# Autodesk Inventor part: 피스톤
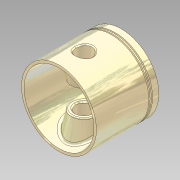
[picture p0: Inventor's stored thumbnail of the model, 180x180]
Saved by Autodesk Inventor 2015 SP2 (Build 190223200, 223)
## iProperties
Manager: KYOUNG IL JANG
Company: 한국ATC센터
Created: 2012-10
Part Number: 피스톤
Document SubType Name: Modeling
Density: 1 g/cm^3
Checked By: KYOUNG IL JANG
Vendor: CBT Solutions
Designer: KYOUNG IL JANG
Material: 일반
Appearance: _시험_금속-티타늄(광택)
Author: KYOUNG IL JANG
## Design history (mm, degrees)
sketch "스케치1"
  geometry: L1 (0, 0)-(0, 50); L2 (0, 50)-(30, 50); L3 (30, 50)-(30, 45); L4 (30, 45)-(28, 45); L5 (28, 45)-(28, 44); L6 (28, 44)-(30, 44); L7 (30, 44)-(30, 43); L8 (30, 43)-(28, 43); L9 (28, 43)-(28, 42); L10 (28, 42)-(30, 42); L11 (30, 42)-(30, 0); L12 (30, 0)-(28, 0); L13 (28, 0)-(23, 45); L14 (23, 45)-(0, 45)
  constraints: 28 end point, 10 parallel, 5 collinear, 2 perpendicular, 2 point on line, 1 vertical
  dimensions: "d0" = 50 distance of L1.start L1.end; "d1" = 60 diameter of L3 L1; "d2" = 5 distance between parallel lines of L2 L14; "d3" = 2 distance of L11.end L12.end; "d5" = 5 distance of L2.end L3.end; "d6" = 1 distance of L4.end L5.end; "d7" = 2 distance of L9.end L10.end; "d26" = 46 diameter of L13.end L1
revolve "회전1" sketch "스케치1" stored, may be unused: angle "d8" = 90 deg
node "작업 평면1"
sketch "스케치2"
  geometry: L1 (-28, 0)-(28, 0) reference; C1 r 10 at (0, 20); C2 r 6.5 at (0, 20); 1 further point
  constraints: 2 centre point, 1 coincident, 1 vertical alignment
  dimensions: "d10" = 20 diameter of C1; "d13" = 20 distance from line of C1.centre L1; "d14" = 13 diameter of C2
extrude "돌출1" join sketch "스케치2" stored distance "d11" = 10; taper "d12" = 12 deg
extrude "돌출2" cut sketch "스케치2" stored distance "d15" = 10; taper "d16" = 0 deg
fillet "모깎기1" dims "d17" = 2, "d21" = 3
chamfer "모따기1" distance "d18" = 1; stored, may be unused: second distance "d19" = 2, angle "d20" = 45 deg
chamfer "모따기2" distance "d22" = 1; stored, may be unused: second distance "d23" = 2, angle "d24" = 45 deg
fillet "모깎기2" dims "d25" = 1
node "솔리드1"
mirror "대칭1"
